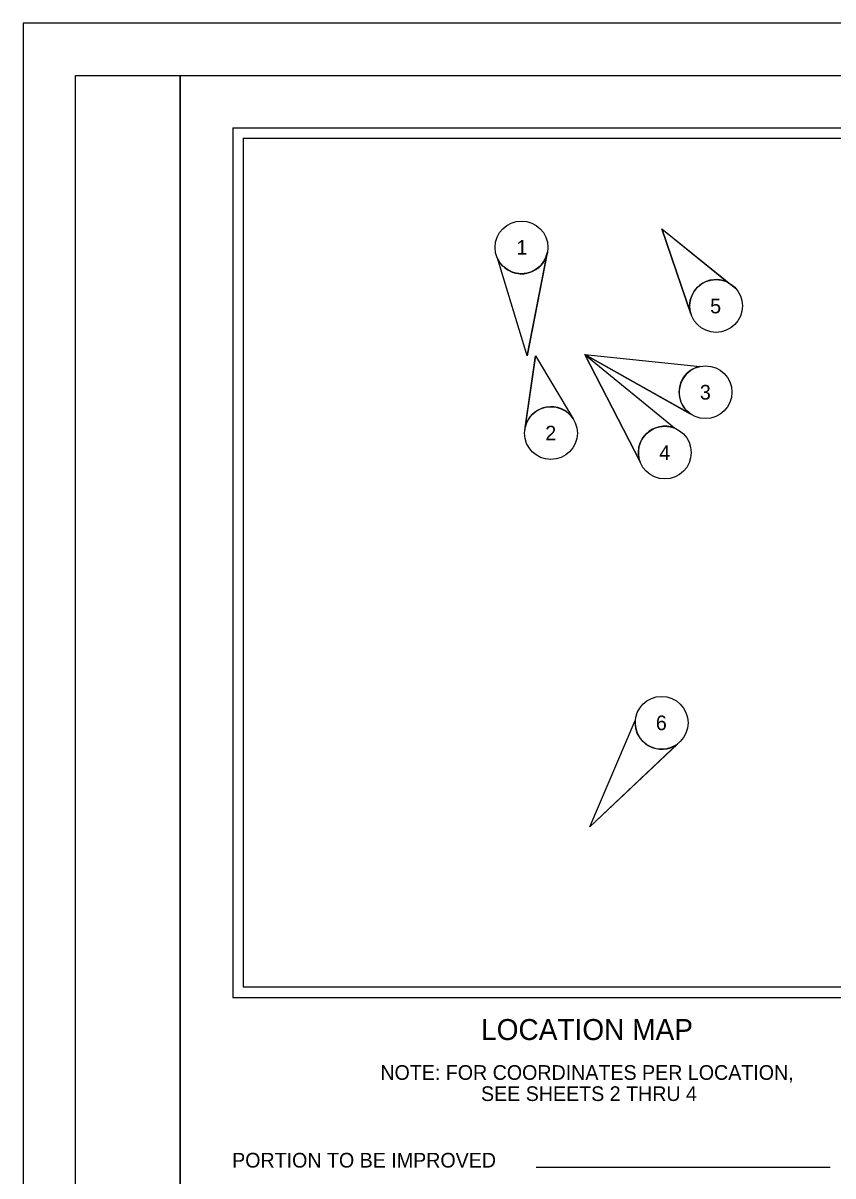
# Model space of a CAD drawing. Extents: x -10 to 89.7, y -4.8 to 22.
# Drawn here: x 0 to 7.72, y 11 to 22 of the extents above; entities that cross this region are included whole.
import ezdxf

# ---------------------------------------------------------------- set-up
doc = ezdxf.new("R2010")
doc.units = 0
for name, color, linetype in [('GM_X_Interstate_Location', 7, 'Continuous'), ('GM_X_Minor_Lake', 7, 'Continuous'), ('GM_X_Minor_River', 7, 'Continuous'), ('GM_X_Minor_River_Text', 7, 'Continuous'), ('SH_Text', 7, 'Continuous')]:
    doc.layers.add(name, color=color, linetype=linetype)

msp = doc.modelspace()

# ---------------------------------------------------------------- linework, layer by layer
at = {"layer": 'GM_X_Interstate_Location'}
for p, q in [((6.093, 20.035), (6.369, 19.225)), ((6.093, 20.035), (6.798, 19.467)), ((4.807, 18.823), (5.002, 19.817)), ((4.807, 18.823), (4.525, 19.755)), ((4.889, 18.823), (4.784, 18.105)), ((4.889, 18.823), (5.247, 18.224)), ((5.358, 18.837), (6.363, 18.272)), ((5.358, 18.837), (6.458, 18.723)), ((5.358, 18.837), (5.886, 17.812)), ((5.358, 18.837), (6.213, 18.136)), ((5.405, 14.329), (5.84, 15.345)), ((5.405, 14.329), (6.242, 15.12))]:
    msp.add_line(p, q, dxfattribs=at)
for centre in [(4.754, 19.859), (6.61, 19.3), (6.51, 18.477), (5.035, 18.087), (6.121, 17.901), (6.091, 15.322)]:
    msp.add_circle(centre, 0.252, dxfattribs=at)
at = {"layer": 'GM_X_Minor_Lake'}
for p, q in [((2, 21), (9, 21)), ((2, 21), (2, 12.701)), ((2.1, 20.9), (2.1, 12.801)), ((2.1, 20.9), (8.9, 20.9)), ((2.1, 12.801), (8.9, 12.801)), ((2, 12.701), (9, 12.701)), ((7.7, 11.078), (4.894, 11.078))]:
    msp.add_line(p, q, dxfattribs=at)
at = {"layer": 'GM_X_Minor_River'}
for points in [[(0.5, 21.5), (1.5, 21.5), (1.5, 0.5), (0.5, 0.5)], [(1.5, 21.5), (33.5, 21.5), (33.5, 0.5), (1.5, 0.5)]]:
    msp.add_lwpolyline(points, close=True, dxfattribs=at)
at = {"layer": 'GM_X_Minor_River_Text'}
for points in [[(6.369, 19.225), (6.369, 19.225), (6.093, 20.035), (6.733, 19.519)], [(5, 19.804), (4.807, 18.823), (4.525, 19.755)], [(4.789, 18.139), (4.889, 18.823), (5.247, 18.224), (5.247, 18.224)], [(6.361, 18.273), (5.358, 18.837), (6.458, 18.723)], [(5.885, 17.814), (5.358, 18.837), (6.213, 18.136)], [(6.241, 15.119), (5.405, 14.329), (5.84, 15.345)]]:
    msp.add_lwpolyline(points, dxfattribs=at)
for centre, major_axis, ratio, start_param, end_param in [((4.754, 19.859), (0, 0.252), 0.999197, 1.999137, 4.491357), ((6.61, 19.3), (0, 0.252), 0.999197, 5.770684, 8.156887), ((6.51, 18.477), (-0.147, -0.205), 0.999122, 3.977083, 6.275668), ((5.035, 18.087), (0, 0.252), 0.999197, 5.284631, 7.646734), ((6.121, 17.901), (-0.236, -0.089), 0.999122, 3.977083, 6.275668), ((6.091, 15.322), (0.152, -0.202), 0.999122, 3.977083, 6.275668)]:
    msp.add_ellipse(centre, major_axis=major_axis, ratio=ratio, start_param=start_param, end_param=end_param, dxfattribs=at)
at = {"layer": 'SH_Text'}
msp.add_lwpolyline([(0, 0), (34, 0), (34, 22), (0, 22)], close=True, dxfattribs=at)

# ---------------------------------------------------------------- texts
at = {"layer": 'GM_X_Interstate_Location'}
for s, p in [('1', (4.707, 19.789)), ('5', (6.554, 19.23)), ('3', (6.456, 18.407)), ('2', (4.981, 18.017)), ('4', (6.068, 17.831)), ('6', (6.036, 15.252))]:
    msp.add_text(s, height=0.14, dxfattribs=at).set_placement(p)
at = {"layer": 'GM_X_Minor_River_Text'}
for s, height, p in [('LOCATION MAP', 0.2, (4.369, 12.295)), ('NOTE: FOR COORDINATES PER LOCATION, ', 0.14, (3.408, 11.915)), ('SEE SHEETS 2 THRU 4', 0.14, (4.368, 11.713)), ('PORTION TO BE IMPROVED', 0.14, (1.994, 11.078))]:
    msp.add_text(s, height=height, dxfattribs=at).set_placement(p)

doc.saveas('drawing.dxf')
